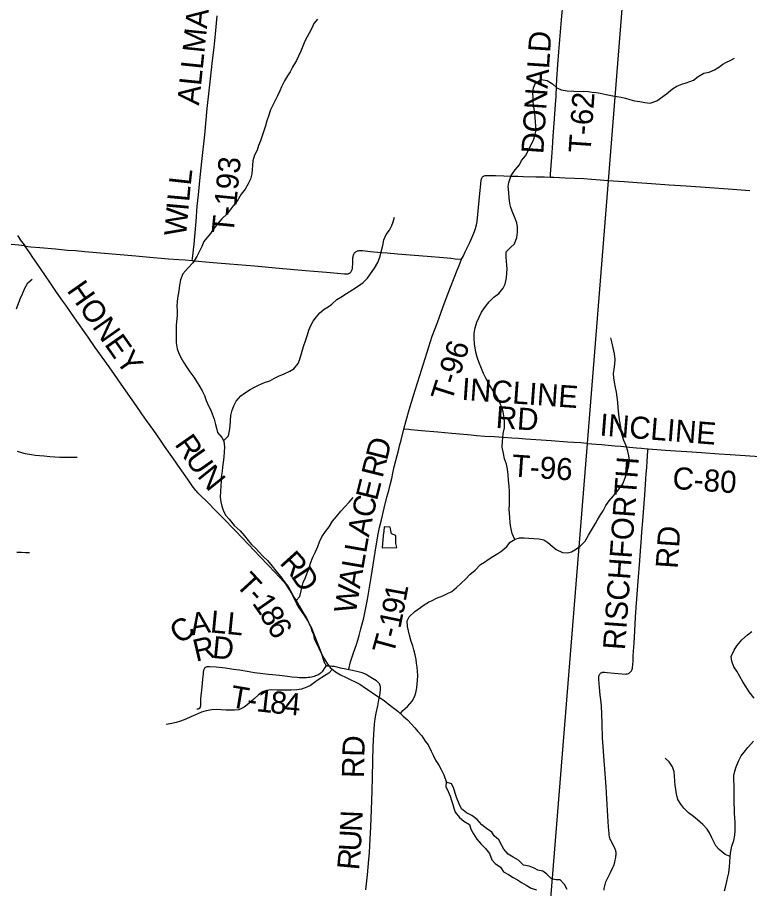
# Model space of a CAD drawing. Extents: x 1451455 to 1749751, y 218250 to 574981.
# Drawn here: x 1596296 to 1606243, y 326004 to 337847 of the extents above; entities that cross this region are included whole.
import ezdxf

# ---------------------------------------------------------------- set-up
doc = ezdxf.new("R2010")
doc.units = 0
for name, color, linetype in [('GM_X_County_Road', 7, 'Continuous'), ('GM_X_County_Road_Text', 7, 'Continuous'), ('GM_X_Minor_Lake', 7, 'Continuous'), ('GM_X_Minor_River', 7, 'Continuous'), ('GM_X_Township', 7, 'Continuous'), ('GM_X_Township_Road', 7, 'Continuous'), ('GM_X_Township_Road_Text', 7, 'Continuous')]:
    doc.layers.add(name, color=color, linetype=linetype)

msp = doc.modelspace()

# ---------------------------------------------------------------- linework, layer by layer
at = {"layer": 'GM_X_County_Road'}
for points in [[(1602331, 334561), (1602355, 334608), (1602380, 334658), (1602441, 334785), (1602484, 334881), (1602506, 334935), (1602520, 334978), (1602532, 335026), (1602541, 335074), (1602552, 335168), (1602579, 335452), (1602590, 335580), (1602597, 335639), (1602599, 335650), (1602604, 335662), (1602609, 335671), (1602615, 335680), (1602621, 335684), (1602627, 335688), (1602632, 335691), (1602639, 335695), (1602649, 335698), (1602662, 335700), (1602676, 335700), (1602696, 335700), (1602791, 335696), (1602906, 335693), (1602991, 335690), (1603096, 335687), (1603168, 335686), (1603341, 335682), (1603407, 335680), (1603459, 335679), (1603537, 335676)], [(1603537, 335676), (1603582, 335674), (1603738, 335666), (1603990, 335655), (1604095, 335647), (1604213, 335639), (1604314, 335632)], [(1604314, 335632), (1604537, 335617), (1604717, 335605), (1604910, 335591), (1605149, 335573), (1605381, 335557), (1605702, 335534), (1605951, 335517), (1606245, 335494)], [(1596296, 334883), (1596346, 334807), (1596373, 334772), (1596398, 334740)], [(1596398, 334740), (1596437, 334735), (1596480, 334730), (1596599, 334719), (1596811, 334699), (1596978, 334685), (1597083, 334677), (1597213, 334665), (1597906, 334607), (1598047, 334594), (1598347, 334567), (1598491, 334558), (1598573, 334552), (1598672, 334543)], [(1598672, 334543), (1598707, 334539), (1598903, 334522), (1599011, 334511), (1599177, 334496), (1599517, 334468), (1599851, 334439), (1600210, 334408), (1600324, 334399), (1600494, 334383), (1600644, 334368), (1600739, 334359), (1600752, 334359), (1600765, 334360), (1600777, 334361), (1600790, 334363), (1600797, 334365), (1600804, 334368), (1600810, 334371), (1600815, 334374), (1600820, 334379), (1600826, 334385), (1600832, 334392), (1600836, 334400), (1600840, 334410), (1600843, 334421), (1600846, 334431), (1600848, 334447), (1600849, 334458), (1600851, 334492), (1600854, 334578), (1600856, 334592), (1600858, 334605), (1600860, 334615), (1600865, 334627), (1600870, 334636), (1600876, 334645), (1600883, 334652), (1600892, 334659), (1600899, 334664), (1600906, 334668), (1600916, 334672), (1600926, 334675), (1600938, 334677), (1600950, 334678), (1600967, 334678), (1600986, 334677), (1601094, 334665), (1601235, 334653), (1601320, 334646), (1601460, 334635), (1601862, 334601), (1602084, 334581), (1602182, 334572), (1602244, 334567), (1602331, 334561)], [(1604030, 332055), (1604232, 332040), (1604411, 332025), (1604496, 332017), (1604610, 332006), (1604708, 331997), (1604774, 331991), (1604852, 331984), (1604865, 331983)], [(1604865, 331983), (1605101, 331965), (1605235, 331956), (1605392, 331944), (1605588, 331931), (1605830, 331915), (1605977, 331904), (1606452, 331874)]]:
    msp.add_lwpolyline(points, dxfattribs=at)
at = {"layer": 'GM_X_Minor_Lake'}
for points in [[(1601452, 330643), (1601436, 330695), (1601439, 330741), (1601438, 330803), (1601378, 330828), (1601358, 330917), (1601278, 330920), (1601273, 330864), (1601264, 330806), (1601252, 330636)], [(1601252, 330636), (1601452, 330643)], [(1603764, 325993), (1603729, 326058), (1603668, 326123), (1603616, 326125), (1603553, 326136), (1603487, 326199), (1603436, 326240), (1603366, 326255), (1603315, 326280), (1603247, 326311), (1603171, 326322), (1603103, 326391), (1603033, 326430), (1602962, 326471), (1602905, 326538), (1602876, 326591), (1602837, 326666), (1602773, 326721), (1602740, 326771), (1602671, 326820), (1602604, 326871), (1602541, 326942), (1602468, 326998), (1602398, 327033), (1602331, 327088), (1602298, 327158), (1602267, 327233), (1602242, 327301), (1602219, 327380), (1602192, 327430), (1602122, 327449), (1602115, 327393), (1602150, 327325), (1602176, 327262), (1602195, 327200), (1602210, 327149), (1602223, 327097), (1602242, 327043), (1602301, 326972), (1602363, 326919), (1602436, 326874), (1602455, 326813), (1602494, 326747), (1602537, 326676), (1602598, 326609), (1602653, 326550), (1602710, 326481), (1602743, 326396), (1602786, 326346), (1602859, 326297), (1602900, 326234), (1602968, 326195), (1603029, 326156), (1603089, 326123), (1603146, 326086), (1603208, 326049), (1603277, 326010), (1603347, 325987)]]:
    msp.add_lwpolyline(points, dxfattribs=at)
at = {"layer": 'GM_X_Minor_River'}
for points in [[(1600374, 337821), (1600323, 337764), (1600294, 337700), (1600261, 337634), (1600233, 337583), (1600202, 337525), (1600173, 337457), (1600146, 337390), (1600113, 337320), (1600086, 337262), (1600035, 337169), (1600000, 337109), (1599963, 337052), (1599925, 336984), (1599883, 336903), (1599859, 336847), (1599828, 336779), (1599793, 336708), (1599762, 336646), (1599735, 336592), (1599706, 336504), (1599685, 336443), (1599666, 336375), (1599639, 336293), (1599622, 336237), (1599599, 336169), (1599570, 336106), (1599552, 336042), (1599517, 335976), (1599494, 335898), (1599491, 335836), (1599486, 335778), (1599479, 335722), (1599464, 335648), (1599431, 335585), (1599392, 335511), (1599337, 335444), (1599282, 335351), (1599229, 335285), (1599188, 335232), (1599144, 335178), (1599075, 335109), (1599008, 335036), (1598961, 334968), (1598918, 334911), (1598869, 334852), (1598829, 334800), (1598802, 334734), (1598759, 334649), (1598734, 334597), (1598681, 334512), (1598616, 334445), (1598541, 334363), (1598510, 334278), (1598499, 334206), (1598488, 334128), (1598472, 334032), (1598465, 333980), (1598463, 333924), (1598468, 333852), (1598467, 333793), (1598456, 333708), (1598453, 333657), (1598452, 333569), (1598452, 333473), (1598452, 333423), (1598466, 333343), (1598486, 333292), (1598517, 333226), (1598550, 333159), (1598591, 333098), (1598640, 333030), (1598693, 332957), (1598724, 332906), (1598773, 332823), (1598806, 332769), (1598837, 332706), (1598862, 332640), (1598893, 332569), (1598922, 332507), (1598942, 332456), (1598970, 332384), (1598985, 332315), (1598999, 332265), (1599014, 332205), (1599075, 332138), (1599098, 332087), (1599109, 332005), (1599106, 331941), (1599101, 331869), (1599092, 331801), (1599083, 331735), (1599078, 331679), (1599065, 331597), (1599063, 331543), (1599058, 331477), (1599053, 331407), (1599052, 331327), (1599059, 331260), (1599072, 331202), (1599091, 331148)], [(1604048, 336838), (1604104, 336832), (1604158, 336825), (1604212, 336816), (1604294, 336799), (1604387, 336781), (1604441, 336771), (1604497, 336762), (1604555, 336747), (1604616, 336730), (1604678, 336715), (1604754, 336704), (1604822, 336691), (1604893, 336680), (1604984, 336713), (1605113, 336807), (1605198, 336874), (1605254, 336913), (1605321, 336938), (1605383, 336957), (1605433, 336975), (1605483, 336994), (1605544, 337043), (1605623, 337090), (1605693, 337103), (1605767, 337134), (1605824, 337170), (1605878, 337213), (1605928, 337240), (1605979, 337261), (1606039, 337293)], [(1603055, 330751), (1603017, 330831), (1602998, 330913), (1602989, 330977), (1602984, 331051), (1602981, 331108), (1602977, 331158), (1602980, 331226), (1602983, 331400), (1602978, 331476), (1602969, 331555), (1602962, 331629), (1602953, 331705), (1602940, 331775), (1602915, 331848), (1602898, 331918), (1602883, 332003), (1602885, 332081), (1602889, 332137), (1602896, 332191), (1602913, 332269), (1602914, 332347), (1602911, 332403), (1602896, 332485), (1602879, 332546), (1602854, 332600), (1602821, 332665), (1602792, 332723), (1602737, 332808), (1602698, 332873), (1602661, 332945), (1602630, 333008), (1602591, 333097), (1602568, 333153), (1602543, 333230), (1602524, 333296), (1602515, 333354), (1602508, 333405), (1602501, 333485), (1602502, 333555), (1602513, 333627), (1602536, 333703), (1602569, 333772), (1602602, 333840), (1602653, 333915), (1602707, 333981), (1602770, 334042), (1602837, 334095), (1602894, 334168), (1602923, 334222), (1602940, 334308), (1602945, 334370), (1602948, 334428), (1602946, 334478), (1602941, 334534), (1602934, 334589), (1602937, 334659), (1602996, 334718), (1603048, 334771), (1603083, 334857), (1603090, 334927), (1603091, 334997), (1603082, 335053), (1603049, 335136), (1603019, 335214), (1603001, 335265), (1602986, 335319), (1602975, 335395), (1602972, 335466), (1602965, 335548), (1602974, 335604), (1603005, 335697), (1603060, 335777), (1603119, 335844), (1603146, 335902), (1603199, 335967), (1603236, 336031), (1603273, 336110), (1603306, 336180), (1603325, 336238), (1603338, 336300), (1603339, 336368), (1603335, 336430), (1603332, 336480), (1603327, 336548), (1603314, 336629), (1603305, 336701), (1603302, 336753), (1603299, 336821), (1603306, 336891), (1603333, 336955), (1603411, 337002), (1603491, 336989), (1603564, 336944), (1603626, 336889), (1603681, 336862), (1603763, 336851), (1603855, 336843), (1603919, 336842), (1603981, 336845), (1604048, 336838)], [(1599097, 332089), (1599163, 332160), (1599178, 332226), (1599185, 332290), (1599190, 332366), (1599197, 332434), (1599212, 332508), (1599235, 332568), (1599268, 332632), (1599329, 332701), (1599383, 332740), (1599456, 332787), (1599518, 332819), (1599570, 332846), (1599653, 332885), (1599727, 332908), (1599788, 332941), (1599844, 332968), (1599920, 333001), (1599997, 333040), (1600053, 333071), (1600108, 333143), (1600133, 333202), (1600156, 333278), (1600183, 333374), (1600214, 333464), (1600235, 333531), (1600254, 333597), (1600281, 333661), (1600316, 333717), (1600361, 333778), (1600406, 333832), (1600462, 333881), (1600519, 333912), (1600569, 333947), (1600636, 334011), (1600688, 334042), (1600767, 334095), (1600854, 334146), (1600930, 334197), (1600991, 334244), (1601050, 334301), (1601094, 334361), (1601149, 334436), (1601192, 334513), (1601226, 334601), (1601238, 334659), (1601260, 334747), (1601275, 334823), (1601306, 334894), (1601350, 334954), (1601383, 335016), (1601402, 335069), (1601419, 335133)], [(1596282, 333885), (1596313, 333971), (1596338, 334029), (1596363, 334091), (1596396, 334166), (1596439, 334238), (1596498, 334289)], [(1601500, 328383), (1601532, 328424), (1601595, 328481), (1601658, 328552), (1601689, 328612), (1601708, 328665), (1601723, 328731), (1601725, 328783), (1601730, 328835), (1601735, 328903), (1601732, 328962), (1601725, 329016), (1601719, 329068), (1601714, 329118), (1601699, 329181), (1601682, 329251), (1601667, 329303), (1601647, 329362), (1601621, 329448), (1601608, 329506), (1601594, 329567), (1601590, 329645), (1601616, 329699), (1601693, 329770), (1601770, 329825), (1601820, 329860), (1601881, 329897), (1601939, 329924), (1601991, 329950), (1602074, 329985), (1602138, 330014), (1602197, 330045), (1602263, 330098), (1602320, 330153), (1602389, 330214), (1602444, 330272), (1602514, 330333), (1602589, 330412), (1602642, 330443), (1602692, 330477), (1602755, 330520), (1602825, 330561), (1602878, 330594), (1602944, 330655), (1602989, 330713), (1603056, 330752), (1603118, 330771), (1603180, 330772), (1603242, 330767), (1603312, 330764), (1603378, 330759), (1603447, 330744), (1603501, 330711), (1603560, 330658), (1603613, 330612), (1603703, 330572), (1603767, 330569), (1603823, 330583), (1603879, 330614), (1603942, 330657), (1604009, 330726), (1604056, 330808), (1604097, 330875), (1604150, 330967), (1604176, 331018), (1604219, 331086), (1604252, 331141), (1604291, 331213), (1604334, 331274), (1604395, 331344), (1604456, 331421), (1604519, 331508), (1604554, 331586), (1604585, 331680), (1604604, 331755), (1604611, 331827), (1604604, 331888), (1604591, 331952), (1604566, 332022), (1604533, 332095), (1604506, 332180), (1604497, 332230), (1604492, 332280), (1604477, 332376), (1604466, 332455), (1604458, 332539), (1604451, 332615), (1604444, 332683), (1604435, 332754), (1604423, 332814), (1604407, 332888), (1604397, 332947), (1604396, 333005), (1604403, 333061), (1604414, 333137), (1604419, 333197), (1604410, 333275), (1604391, 333353), (1604378, 333418), (1604359, 333490)], [(1596291, 331952), (1596351, 331931), (1596402, 331920), (1596486, 331905), (1596538, 331898), (1596594, 331893), (1596660, 331888), (1596736, 331879), (1596803, 331874), (1596873, 331871), (1596931, 331868), (1596989, 331871), (1597057, 331868), (1597109, 331868)], [(1600082, 329922), (1600131, 329974), (1600151, 330050), (1600163, 330110), (1600180, 330166), (1600209, 330232), (1600230, 330284), (1600253, 330349), (1600278, 330427), (1600309, 330511), (1600340, 330575), (1600377, 330654), (1600402, 330718), (1600431, 330784), (1600480, 330857), (1600530, 330922), (1600577, 331000), (1600630, 331063), (1600689, 331135), (1600744, 331192), (1600805, 331259), (1600858, 331322)], [(1599091, 331148), (1599122, 331079), (1599173, 331024), (1599242, 330939), (1599323, 330866), (1599380, 330799), (1599429, 330736), (1599476, 330683), (1599533, 330626), (1599578, 330576), (1599632, 330523), (1599693, 330466), (1599756, 330389), (1599807, 330326), (1599873, 330243), (1599932, 330162), (1599976, 330109), (1600005, 330050), (1600051, 329964), (1600093, 329907), (1600124, 329846), (1600157, 329792), (1600186, 329737), (1600223, 329683), (1600249, 329628), (1600278, 329572), (1600297, 329507), (1600318, 329457), (1600329, 329399), (1600389, 329274), (1600422, 329203), (1600457, 329136), (1600502, 329065), (1600546, 329011), (1600617, 328952), (1600686, 328909), (1600761, 328875), (1600827, 328844), (1600883, 328816), (1600948, 328783), (1601025, 328729), (1601087, 328690), (1601140, 328650), (1601215, 328604), (1601277, 328561), (1601334, 328517), (1601411, 328459), (1601464, 328414), (1601537, 328349), (1601595, 328296), (1601646, 328246), (1601695, 328189), (1601734, 328138), (1601789, 328079), (1601836, 328008), (1601874, 327958), (1601916, 327873), (1601944, 327819), (1601977, 327752), (1602020, 327681), (1602051, 327621), (1602090, 327550), (1602126, 327448)], [(1596290, 330577), (1596352, 330578), (1596405, 330575), (1596461, 330575)], [(1606307, 328593), (1606238, 328678), (1606191, 328751), (1606150, 328814), (1606111, 328889), (1606068, 328959), (1606031, 329020), (1606002, 329097), (1605993, 329161), (1606032, 329246), (1606069, 329306), (1606136, 329387), (1606215, 329454), (1606273, 329501)], [(1600576, 328985), (1600526, 328933), (1600470, 328898), (1600383, 328841), (1600333, 328805), (1600276, 328764), (1600226, 328741), (1600156, 328716), (1600090, 328707), (1600014, 328700), (1599820, 328703), (1599750, 328706), (1599680, 328697), (1599626, 328677), (1599573, 328638), (1599508, 328579), (1599442, 328520), (1599375, 328471), (1599305, 328436), (1599247, 328428), (1599133, 328430), (1599063, 328435), (1599001, 328438), (1598935, 328433), (1598861, 328422), (1598795, 328401), (1598716, 328366), (1598650, 328337), (1598583, 328306), (1598511, 328281), (1598451, 328264), (1598395, 328250), (1598317, 328233)], [(1605902, 325972), (1605921, 326040), (1605936, 326100), (1605947, 326162), (1605960, 326220), (1605969, 326302), (1605976, 326362), (1605979, 326434), (1605985, 326486), (1606001, 326580), (1606028, 326658), (1606041, 326730), (1606045, 326790), (1606048, 326846), (1606047, 326910), (1606044, 326962), (1606039, 327034), (1606038, 327095), (1606035, 327159), (1606033, 327213), (1606034, 327279), (1606035, 327331), (1606034, 327417), (1606031, 327471), (1606030, 327543), (1606043, 327601), (1606062, 327661), (1606093, 327737), (1606128, 327807), (1606170, 327860), (1606217, 327921), (1606296, 328010)], [(1605979, 326440), (1605911, 326467), (1605828, 326535), (1605785, 326585), (1605758, 326638), (1605730, 326696), (1605699, 326761), (1605668, 326811), (1605607, 326874), (1605534, 326939), (1605481, 326982), (1605415, 327035), (1605350, 327098), (1605309, 327151), (1605270, 327216), (1605251, 327292), (1605240, 327352), (1605231, 327411), (1605228, 327465), (1605225, 327539), (1605217, 327591), (1605198, 327660), (1605151, 327728), (1605096, 327775)]]:
    msp.add_lwpolyline(points, dxfattribs=at)
at = {"layer": 'GM_X_Township'}
for points in [[(1603446, 324685), (1604039, 332057), (1604327, 335626), (1604590, 338933), (1605120, 345606), (1605455, 350781)], [(1615589, 321107), (1615010, 321279), (1612831, 321883), (1608561, 323145), (1605657, 324014), (1605008, 324208), (1603446, 324685), (1604039, 332057), (1604327, 335626), (1604590, 338933), (1605120, 345606), (1605455, 350781)]]:
    msp.add_lwpolyline(points, dxfattribs=at)
at = {"layer": 'GM_X_Township_Road'}
for points in [[(1603537, 335676), (1603540, 335716), (1603549, 335836), (1603557, 335948), (1603565, 336072), (1603574, 336233), (1603594, 336468), (1603607, 336661), (1603613, 336776), (1603619, 336914), (1603625, 337009), (1603639, 337205), (1603651, 337378), (1603686, 337816), (1603709, 338061), (1603728, 338214), (1603789, 338623), (1603812, 338772), (1603837, 338936), (1603844, 338979)], [(1598672, 334543), (1598675, 334570), (1598696, 334766), (1598706, 334867), (1598723, 335073), (1598740, 335282), (1598755, 335435), (1598775, 335631), (1598801, 335886), (1598841, 336251), (1598872, 336607), (1598899, 336849), (1598926, 337094), (1598946, 337260), (1598964, 337400), (1598978, 337527), (1598991, 337667), (1598991, 337671), (1599009, 337867)], [(1596398, 334740), (1596314, 334749), (1596212, 334759)], [(1600497, 329036), (1600493, 329038), (1600488, 329043), (1600484, 329047), (1600480, 329053), (1600474, 329066), (1600464, 329090), (1600421, 329216), (1600381, 329321), (1600322, 329474), (1600289, 329552), (1600266, 329600), (1600237, 329652), (1600200, 329710), (1600159, 329770), (1600122, 329823), (1600093, 329874), (1600073, 329912), (1600018, 330020), (1599995, 330063), (1599971, 330103), (1599946, 330138), (1599912, 330179), (1599861, 330234), (1599707, 330395), (1599584, 330523), (1599517, 330595), (1599259, 330866), (1599082, 331050), (1598979, 331155), (1598898, 331237), (1598852, 331283), (1598808, 331323), (1598787, 331344), (1598746, 331386), (1598733, 331401), (1598721, 331415), (1598672, 331481), (1598615, 331561), (1598554, 331650), (1598477, 331760), (1598447, 331803), (1598296, 332018), (1598240, 332099), (1598147, 332230), (1598051, 332367), (1597984, 332460), (1597908, 332571), (1597856, 332647), (1597705, 332862), (1597613, 332993), (1597541, 333095), (1597447, 333229), (1597388, 333312), (1597354, 333360), (1597256, 333500), (1597072, 333763), (1596954, 333933), (1596915, 333989), (1596829, 334114), (1596745, 334235), (1596610, 334433), (1596560, 334506), (1596507, 334581), (1596463, 334646), (1596398, 334740)], [(1601547, 332251), (1601578, 332368), (1601619, 332513), (1601701, 332779), (1601761, 332978), (1601884, 333369), (1601932, 333512), (1602002, 333700), (1602077, 333903), (1602135, 334063), (1602178, 334180), (1602228, 334309), (1602269, 334412), (1602296, 334476), (1602331, 334561)], [(1600800, 328977), (1600804, 329010), (1600810, 329046), (1600821, 329086), (1600863, 329210), (1600903, 329324), (1600921, 329379), (1600940, 329445), (1600963, 329534), (1601000, 329684), (1601016, 329754), (1601051, 329935), (1601103, 330232), (1601130, 330407), (1601168, 330663), (1601195, 330822), (1601215, 330912), (1601240, 331017), (1601278, 331177), (1601316, 331323), (1601340, 331415), (1601359, 331491), (1601381, 331581), (1601397, 331651), (1601416, 331737), (1601476, 331976), (1601488, 332024), (1601508, 332101), (1601547, 332251)], [(1601642, 332242), (1601612, 332245), (1601547, 332251)], [(1604030, 332055), (1603950, 332062), (1603856, 332068), (1603767, 332075), (1603549, 332089), (1603204, 332114), (1603102, 332121), (1603014, 332127), (1602898, 332135), (1602775, 332144), (1602644, 332152), (1602533, 332161), (1602461, 332167), (1602305, 332181), (1602197, 332192), (1602007, 332209), (1601785, 332228), (1601642, 332242)], [(1604267, 325984), (1604269, 326005), (1604272, 326023), (1604275, 326040), (1604280, 326058), (1604292, 326095), (1604312, 326140), (1604354, 326222), (1604382, 326281), (1604398, 326320), (1604412, 326364), (1604418, 326389), (1604423, 326409), (1604427, 326428), (1604428, 326448), (1604430, 326465), (1604429, 326481), (1604429, 326495), (1604427, 326510), (1604424, 326524), (1604419, 326538), (1604414, 326552), (1604408, 326565), (1604385, 326605), (1604365, 326643), (1604357, 326661), (1604351, 326676), (1604345, 326693), (1604341, 326710), (1604337, 326733), (1604334, 326753), (1604326, 326844), (1604319, 326988), (1604305, 327224), (1604295, 327388), (1604271, 327685), (1604262, 327803), (1604252, 327940), (1604247, 328045), (1604240, 328255), (1604236, 328376), (1604229, 328488), (1604221, 328569), (1604214, 328634), (1604204, 328739), (1604196, 328845), (1604195, 328867), (1604196, 328882), (1604197, 328893), (1604198, 328900), (1604200, 328906), (1604203, 328911), (1604207, 328918), (1604212, 328925), (1604217, 328931), (1604224, 328936), (1604230, 328939), (1604239, 328942), (1604246, 328944), (1604255, 328946), (1604274, 328946), (1604310, 328943), (1604405, 328933), (1604510, 328923), (1604556, 328921), (1604570, 328923), (1604585, 328925), (1604596, 328929), (1604606, 328934), (1604613, 328939), (1604619, 328944), (1604630, 328955), (1604638, 328964), (1604643, 328974), (1604649, 328989), (1604652, 329000), (1604654, 329012), (1604658, 329041), (1604660, 329103), (1604662, 329159), (1604666, 329231), (1604674, 329339), (1604685, 329509), (1604695, 329696), (1604702, 329824), (1604731, 330183), (1604752, 330465), (1604762, 330596), (1604771, 330710), (1604781, 330851), (1604791, 331005), (1604805, 331178), (1604818, 331355), (1604829, 331499), (1604833, 331574), (1604837, 331636), (1604845, 331731), (1604850, 331806), (1604857, 331891), (1604862, 331949), (1604865, 331983)], [(1598735, 328449), (1598746, 328449), (1598758, 328450), (1598767, 328453), (1598775, 328459), (1598781, 328469), (1598785, 328481), (1598786, 328493), (1598787, 328536), (1598789, 328577), (1598794, 328628), (1598797, 328661), (1598802, 328708), (1598805, 328732), (1598811, 328803), (1598816, 328850), (1598822, 328923), (1598824, 328944), (1598825, 328956), (1598827, 328966), (1598829, 328975), (1598832, 328983), (1598834, 328988), (1598838, 328996), (1598844, 329005), (1598850, 329010), (1598856, 329015), (1598861, 329017), (1598865, 329019), (1598872, 329022), (1598880, 329024), (1598891, 329025), (1598905, 329025), (1598995, 329017), (1599122, 329003), (1599233, 328989), (1599314, 328976), (1599418, 328959), (1599518, 328942), (1599629, 328928), (1599707, 328921), (1599763, 328916), (1599857, 328905), (1599965, 328891), (1600026, 328884), (1600098, 328877), (1600125, 328875), (1600156, 328873), (1600177, 328873), (1600199, 328873), (1600222, 328875), (1600244, 328877), (1600268, 328880), (1600289, 328884), (1600310, 328889), (1600331, 328894), (1600348, 328900), (1600362, 328905), (1600377, 328912), (1600391, 328919), (1600404, 328928), (1600416, 328936), (1600427, 328945), (1600436, 328953), (1600444, 328961), (1600454, 328972), (1600468, 328994), (1600490, 329027), (1600497, 329036)], [(1600641, 329012), (1600616, 329018), (1600601, 329022), (1600585, 329024), (1600571, 329025), (1600543, 329026), (1600528, 329028), (1600515, 329030), (1600507, 329032), (1600500, 329034), (1600497, 329036)], [(1600800, 328977), (1600757, 328986), (1600687, 329001), (1600641, 329012)], [(1601208, 328796), (1601201, 328804), (1601192, 328812), (1601185, 328819), (1601174, 328827), (1601121, 328862), (1601062, 328898), (1601033, 328913), (1601015, 328922), (1600978, 328936), (1600927, 328950), (1600847, 328968), (1600800, 328977)], [(1601029, 325987), (1601051, 326189), (1601072, 326401), (1601079, 326493), (1601089, 326677), (1601098, 326844), (1601107, 327076), (1601114, 327332), (1601121, 327516), (1601125, 327745), (1601130, 327930), (1601136, 328105), (1601146, 328240), (1601156, 328313), (1601171, 328387), (1601192, 328489), (1601208, 328572), (1601219, 328627), (1601224, 328665), (1601229, 328705), (1601229, 328718), (1601229, 328731), (1601228, 328742), (1601227, 328752), (1601225, 328762), (1601220, 328775), (1601215, 328786), (1601208, 328795), (1601208, 328796)]]:
    msp.add_lwpolyline(points, dxfattribs=at)

# ---------------------------------------------------------------- texts
at = {"layer": 'GM_X_County_Road_Text'}
for s, rotation, p in [('INCLINE', 355.4187, (1604199, 332164)), ('C-80', 355.8901, (1605188, 331439))]:
    msp.add_text(s, height=300, rotation=rotation, dxfattribs=at).set_placement(p)
at = {"layer": 'GM_X_Township_Road_Text'}
for s, rotation, p in [('ALLMAN', 84.1375, (1598763, 336644)), ('DONALD', 86.143, (1603440, 335985)), ('T-62', 86.1187, (1604082, 335997)), ('T-193', 84.4624, (1599232, 334895)), ('L', 83.6442, (1598650, 335555)), ('L', 84.7169, (1598629, 335333)), ('W', 84.836, (1598587, 334865)), ('I', 84.8335, (1598618, 335211)), ('HONEY', 305.0204, (1596958, 334134)), ('T-96', 72.3486, (1602193, 332608)), ('INCLINE', 355.9025, (1602324, 332649)), ('RD', 356.0571, (1602788, 332267)), ('R', 305.1137, (1598423, 332044)), ('D', 76.0154, (1601316, 331814)), ('U', 305.1827, (1598565, 331842)), ('R', 76.0146, (1601256, 331575)), ('T-96', 356.1063, (1603006, 331607)), ('RISCHFORTH', 85.8286, (1604549, 329241)), ('N', 308.8851, (1598730, 331610)), ('E', 76.0147, (1601180, 331267)), ('C', 76.4238, (1601122, 331028)), ('A', 78.4807, (1601070, 330773)), ('RD', 86.0553, (1605265, 330347)), ('L', 80.0938, (1601032, 330554)), ('R', 312.2102, (1599847, 330425)), ('L', 80.2609, (1600994, 330333)), ('T', 312.8768, (1599247, 330130)), ('D', 303.8315, (1600005, 330251)), ('A', 80.2562, (1600949, 330073)), ('W', 80.2589, (1600890, 329730)), ('1', 79.493, (1601570, 329898)), ('-', 312.7253, (1599400, 329966)), ('1', 304.9675, (1599477, 329884)), ('9', 79.2746, (1601536, 329715)), ('8', 298.858, (1599578, 329740)), ('A', 9.539, (1598667, 329445)), ('L', 354.4822, (1598907, 329488)), ('L', 354.2195, (1599130, 329467)), ('1', 78.3561, (1601497, 329529)), ('C', 34.9805, (1598498, 329317)), ('6', 301.8525, (1599676, 329563)), ('T', 74.6191, (1601403, 329172)), ('-', 75.9109, (1601464, 329396)), ('R', 13.2193, (1598721, 329087)), ('D', 354.4801, (1598935, 329141)), ('T', 350.3221, (1599172, 328474)), ('1', 353.518, (1599534, 328416)), ('8', 353.875, (1599719, 328395)), ('4', 354.9581, (1599909, 328375)), ('-', 352.1795, (1599404, 328434)), ('RD', 88.5244, (1601002, 327504)), ('N', 87.4895, (1600975, 326772)), ('U', 86.8667, (1600960, 326505)), ('R', 84.8137, (1600937, 326248))]:
    msp.add_text(s, height=300, rotation=rotation, dxfattribs=at).set_placement(p)

doc.saveas('drawing.dxf')
